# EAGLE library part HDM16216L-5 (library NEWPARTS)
PIN HEADER
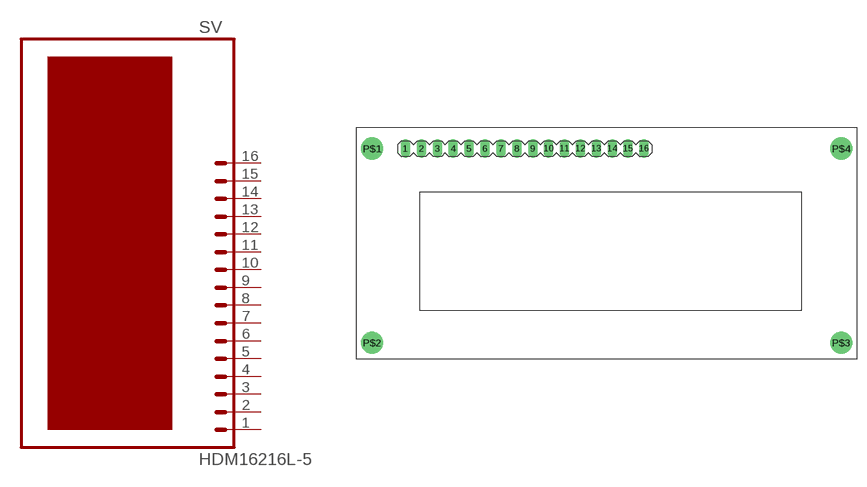
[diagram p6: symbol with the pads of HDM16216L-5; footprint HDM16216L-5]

Designator prefix SV

## HDM16216L-5  [HDM16216L-5]
1  1  pas
2  2  pas
3  3  pas
4  4  pas
5  5  pas
6  6  pas
7  7  pas
8  8  pas
9  9  pas
10  10  pas
11  11  pas
12  12  pas
13  13  pas
14  14  pas
15  15  pas
16  16  pas

## Footprint HDM16216L-5 (pad centres in mm)
PIN HEADER
drill 1.016 long: 1 7.874,33.528; 2 10.414,33.528; 3 12.954,33.528; 4 15.494,33.528; 5 18.034,33.528; 6 20.574,33.528; 7 23.114,33.528; 8 25.654,33.528; 9 28.194,33.528; 10 30.734,33.528; 11 33.274,33.528; 12 35.814,33.528; 13 38.354,33.528; 14 40.894,33.528; 15 43.434,33.528; 16 45.974,33.528
drill 2.54 round: P$1 2.54,33.528; P$2 2.54,2.54; P$3 77.47,2.54; P$4 77.47,33.528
